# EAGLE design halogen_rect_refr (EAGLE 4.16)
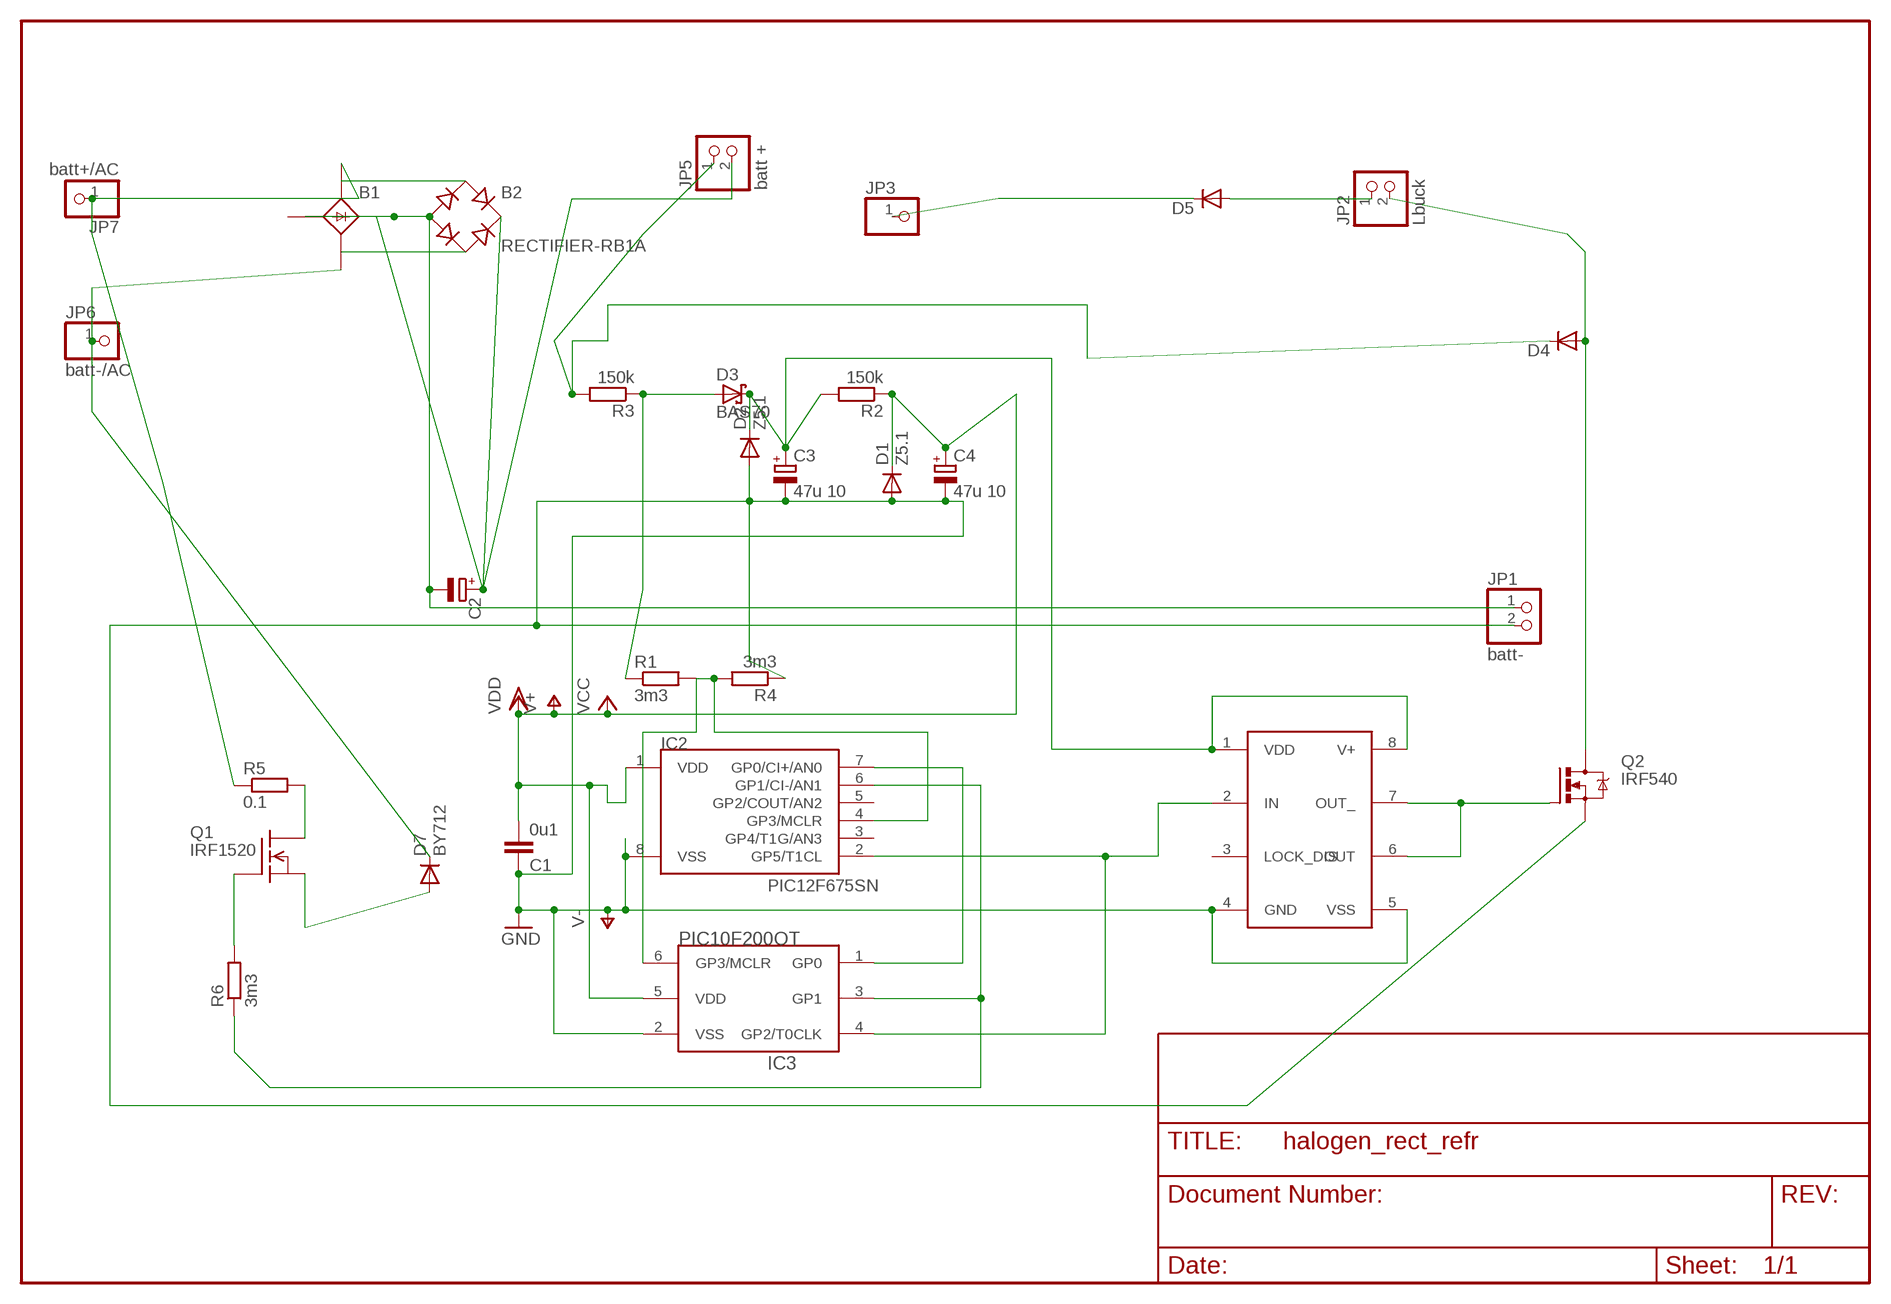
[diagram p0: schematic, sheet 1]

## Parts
B1  B25A-  [B25A-]
B2  RECTIFIER-RB1A  [RB1A]
C1  0u1  C-EUC1206  [C1206]
C2  CPOL-EUE7.5-18  [E7,5-18]
C3  47u 10  CPOL-EUE2,5-6E  [E2,5-6E]
C4  47u 10  CPOL-EUSMCD  [SMC_D]
D1  Z5.1  DIODE-MINIMELF  [MINIMELF]
D2  Z5.1  DIODE-MINIMELF  [MINIMELF]
D3  BAS70  [SOT23]
D4  DIODE-MELF-MLL41  [MELF-MLL41]
D5  DIODE-MELF-MLL41  [MELF-MLL41]
D7  BY712  [SOD61E]
IC1  TC4432X  [SO-08]
IC2  PIC12F675SN  [SO-08]
IC3  PIC10F200OT  [SOT23-6]
JP1  batt-  PINHD-1X2  [1X02]
JP2  Lbuck  PINHD-1X2  [1X02]
JP3  PINHD-1X1  [1X01]
JP5  batt +  PINHD-1X2  [1X02]
JP6  batt-/AC  PINHD-1X1  [1X01]
JP7  batt+/AC  PINHD-1X1  [1X01]
Q1  IRF1520  IRF540  [TO220]
Q2  IRF540  [TO220BV]
R1  3m3  R-EU_R1206  [R1206]
R2  150k  R-EU_R1206  [R1206]
R3  150k  R-EU_R1206  [R1206]
R4  3m3  R-EU_R1206  [R1206]
R5  0.1  R-EU_0613/5V  [P0613V]
R6  3m3  R-EU_R1206  [R1206]

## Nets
N$1: D4.C JP5.1 R3.2
N$2: B1.AC1-(AC1) JP7.1 R5.1
N$3: B1.AC2-(AC2) D7.C JP6.1
N$4: C3.+ D2.C D3.3(C) IC1.1(VDD) IC1.8(V+) R2.2
N$5: D5.A JP2.1
N$6: D3.1(A) R1.1 R3.1
N$7: IC1.6(OUT) IC1.7(OUT_) Q2.G
N$8: B1.AC1 B2.AC1
N$9: D4.A JP2.2 Q2.D
N$10: B1.+ B2.+ C2.+ JP5.2
N$11: B1.AC2 B2.AC2
N$12: IC2.4(GP3/MCLR) IC3.6(GP3/MCLR) R1.2 R4.2
N$13: B1.+1(+) B1.- B2.- C2.- JP1.1
N$14: IC1.2(IN) IC2.2(GP5/T1CL) IC3.4(GP2/T0CLK)
N$15: IC2.7(GP0/CI+/AN0) IC3.1(GP0)
N$16: IC2.6(GP1/CI-/AN1) IC3.3(GP1) R6.1
N$20: D7.A Q1.3(S)
N$21: Q1.2(D) R5.2
N$24: D5.C JP3.1
N$25: Q1.1(G) R6.2
V+: C1.2 C4.+ D1.C IC2.1(VDD) IC3.5(VDD) R2.1 ; supply symbol labelled VCC, VDD
V-: C1.1 C3.- C4.- D1.A D2.A IC1.4(GND) IC1.5(VSS) IC2.8(VSS) IC3.2(VSS) JP1.2 Q2.S R4.1 ; supply symbol labelled GND
Unconnected: B1.-1(-) IC1.3(LOCK_DIS) IC2.3(GP4/T1G/AN3) IC2.5(GP2/COUT/AN2)

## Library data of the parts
B1 = rectifier:B25A-: RECTIFIER 25-A bridge
B2 = rectifier:RECTIFIER-: Rectifier
C1 = rcl:C-EU: CAPACITOR, European symbol
C2-C4 = rcl:CPOL-EU: POLARIZED CAPACITOR, European symbol
D1 D2 D4 D5 = diode:DIODE-: DIODE
D3 = diode:BAS70: Silicon Schottky Diodes
D7 = diode:BY712: DIODE
IC1 = microchip:TC4432
IC2 = microchip-3:PIC12F6*: uPC nW 1k Program Flash memory 2x Timer Comparator 10b A/D converter/ 4xIN
IC3 = microchip-3:PIC10F20*: uPC nW 0,25/0,5k Program Flash memory
JP1 JP2 JP5 = pinhead:PINHD-1X2: PIN HEADER
JP3 JP6 JP7 = pinhead:PINHD-1X1: PIN HEADER
Q1 = transistor-fet:IRF540: N-Channel Enhancement MOSFET (HEXFET); 100V; 28A; 0,077Ohm
Q2 = transistor-power:IRF540: HEXFET Power MOSFET
R1-R6 = rcl:R-EU_: RESISTOR, European symbol

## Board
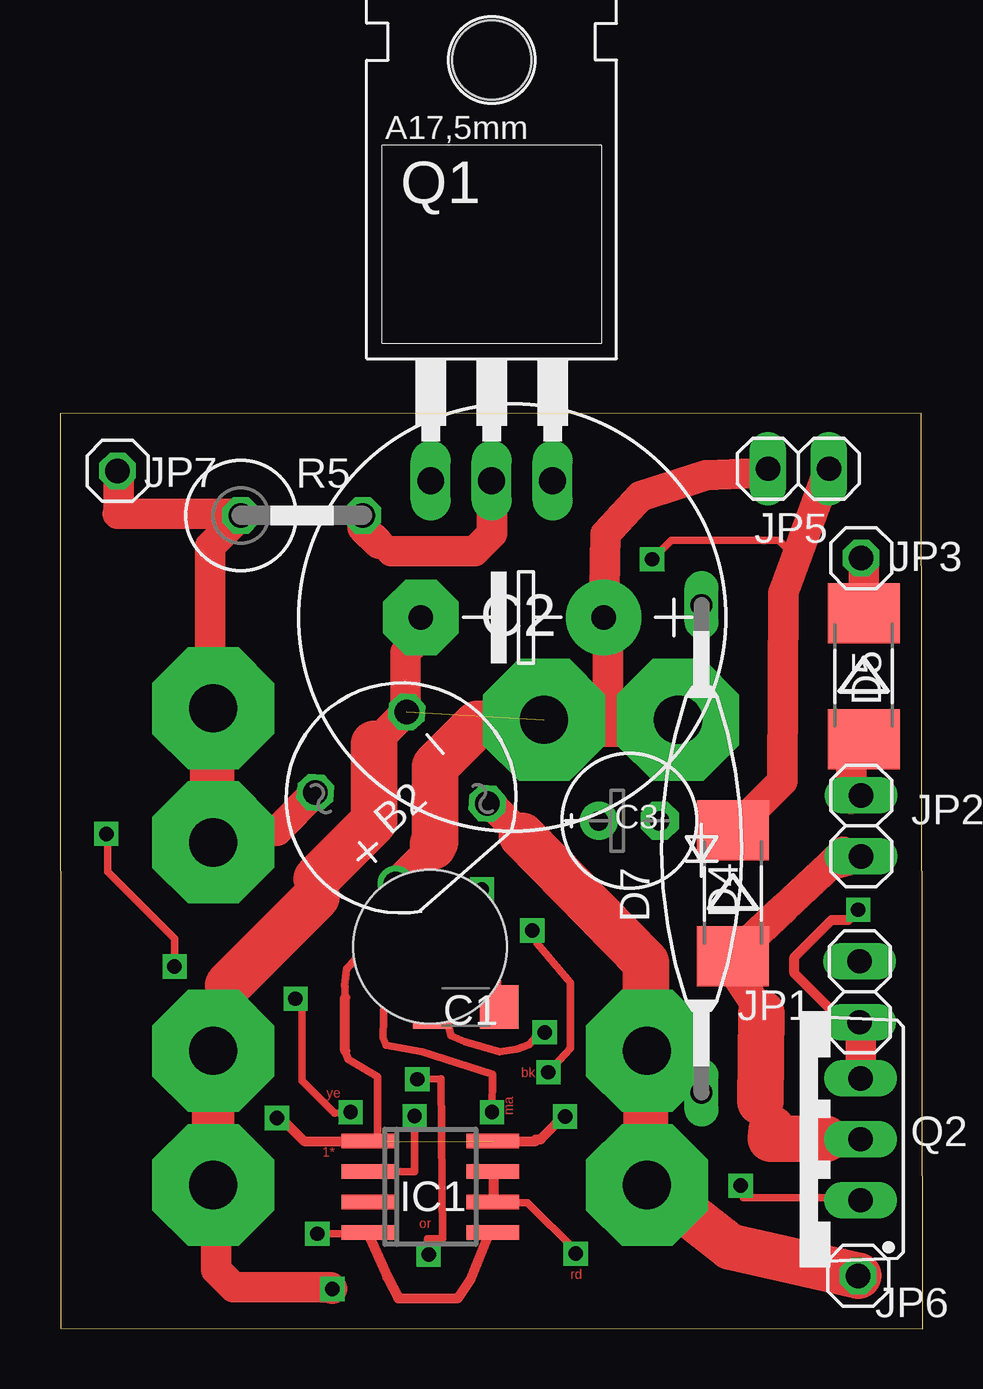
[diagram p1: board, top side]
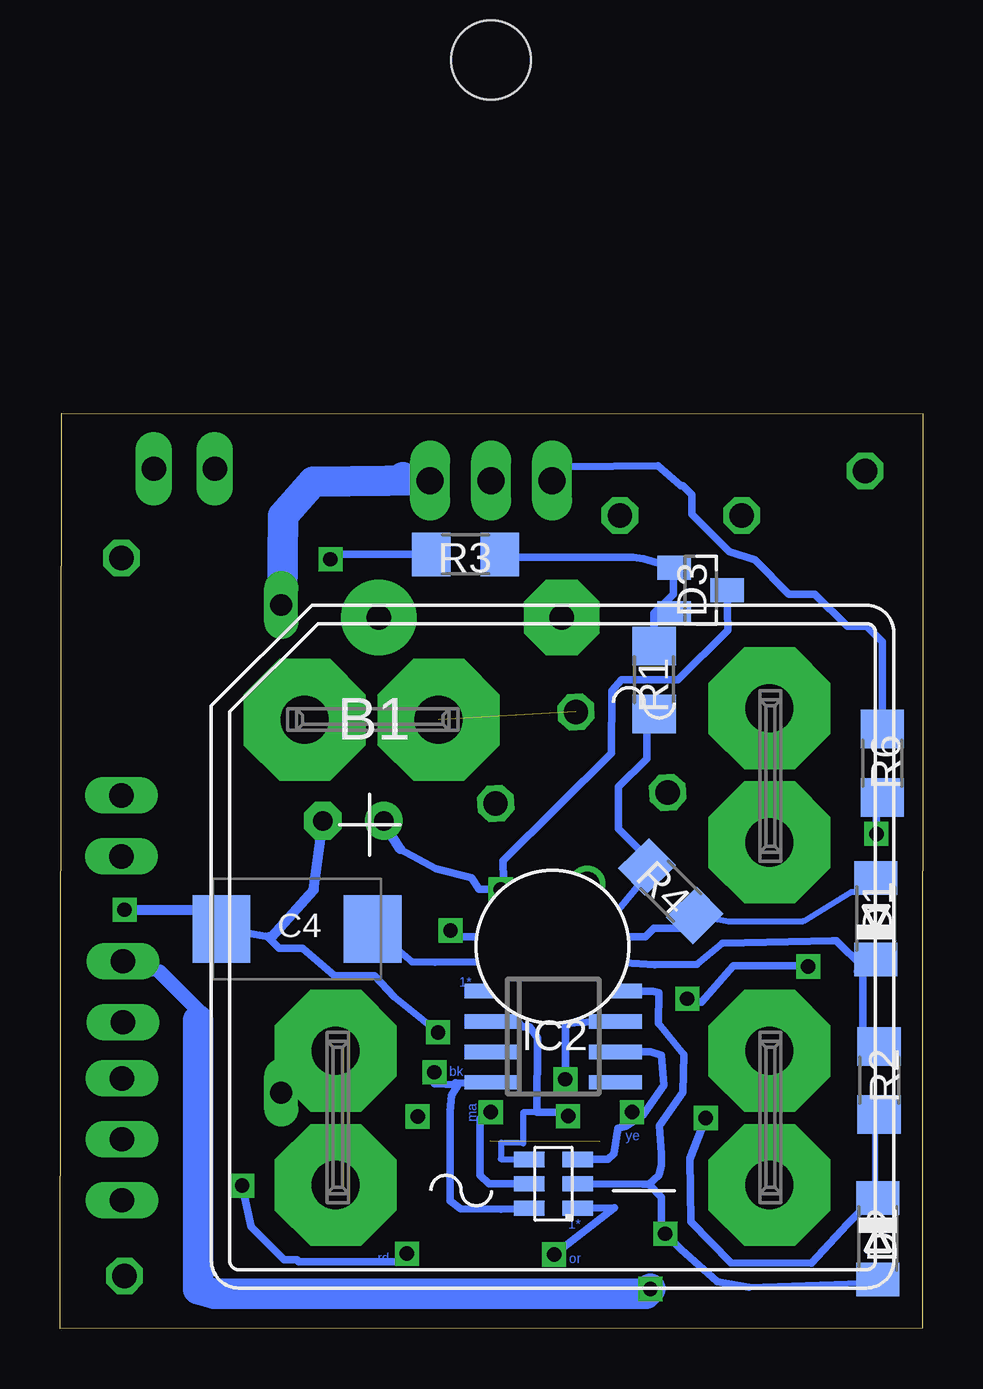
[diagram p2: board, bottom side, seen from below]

Size 35.97 x 38.15 mm. Coordinates in mm from the lower left corner, seen from the top.
Outline: 0.03,0.01 35.97,0 35.9,38.15 0,38.13 0.03,0.01
Copper layers (1*16): Top 0.035mm / dielectric 1.5mm / Bottom 0.035mm
Design rules "default": minimum track width 10mil, minimum drill 24mil, track to track 8mil, track to pad 8mil, pad to pad 8mil, via to via 8mil, smd to smd 8mil, copper to edge 40mil, drill to drill 8mil, minimum pad ring 10mil, minimum via ring 8mil, stop-mask expansion 4mil, vias tented up to drill 0mil, thermal gap 10mil

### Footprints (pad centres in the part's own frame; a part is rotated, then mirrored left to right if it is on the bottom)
B25A- = drill 2.007 pad 5.08 octagon: + -10.338,9.449; +1 -4.75,9.449; - 9.042,-4.343; -1 9.042,-9.931; AC1 9.042,4.343; AC1- 9.042,9.931; AC2 -9.042,-4.343; AC2- -9.042,-9.931 | hole 6.401: 0,0
RB1A = drill 1.016 round: + -2.54,2.54 | drill 1.016 octagon: - 2.54,-2.54; AC1 2.54,2.54; AC2 -2.54,-2.54
C1206 = smd 1.6 x 1.8: 1 -1.4,0; 2 1.4,0
E7,5-18 = drill 1.016 pad 3.15 round: + -3.81,0 | drill 1.016 pad 3.15 octagon: - 3.81,0
E2,5-6E = drill 0.813 pad 1.575 round: + -1.27,0 | drill 0.813 pad 1.575 octagon: - 1.27,0
SMC_D = smd 2.4 x 2.8: + -3.15,0; - 3.15,0
MINIMELF = smd 1.4 x 1.8: A 1.7,0; C -1.7,0
SOT23 = smd 1 x 1.4: 1 -0.95,-1.1; 2 0.95,-1.1; 3 0,1.1
MELF-MLL41 = smd 2.5 x 3: A 2.625,0; C -2.625,0
SOD61E = drill 0.914 long: A 10.16,0; C -10.16,0
SO-08 = smd 0.6 x 2.2: 1 -1.905,-2.6; 2 -0.635,-2.6; 3 0.635,-2.6; 4 1.905,-2.6; 5 1.905,2.6; 6 0.635,2.6; 7 -0.635,2.6; 8 -1.905,2.6
SOT23-6 = smd 0.635 x 1.27: 1 -1.016,-1.016; 2 0,-1.016; 3 1.016,-1.016; 4 1.016,1.016; 5 0,1.016; 6 -1.016,1.016
1X02 = drill 1.016 long: 1 -1.27,0; 2 1.27,0
1X01 = drill 1.016 octagon: 1 0,0
TO220 = drill 1.118 long: 1 -2.54,-6.35; 2 0,-6.35; 3 2.54,-6.35 | hole 3.302: 0,11.176
TO220BV = drill 1.016 long: D 0,-2.54; G -2.54,-2.54; S 2.54,-2.54
R1206 = smd 1.6 x 1.803: 1 -1.422,0; 2 1.422,0
P0613V = drill 1.016 octagon: 1 -2.54,0; 2 2.54,0

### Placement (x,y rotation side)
B1  15.43,15.92 0 bottom
B2  14.22,22.12 131.3 top
C1  16.92,13.41 0 top
C2  18.86,29.64 180 top
C3  23.74,21.17 0 top
C4  26.09,16.66 180 bottom
D1  1.96,17.09 90 bottom
D2  1.87,3.75 270 bottom
D3  9.26,30.77 270 bottom
D4  28.05,18.14 270 top
D5  33.5,27.2 270 top
D7  26.75,20 90 top
IC1  15.44,5.91 270 top
IC2  15.41,12.17 270 bottom
IC3  15.39,6.04 90 bottom
JP1  33.34,14.04 270 top
JP2  33.4,20.95 270 top
JP3  33.4,32.11 0 top
JP5  30.78,35.83 180 top
JP6  33.27,2.2 0 top
JP7  2.4,35.75 0 top
Q1  18,41.69 0 top
Q2  30.84,7.89 90 top
R1  11.2,27.03 270 bottom
R2  1.82,10.35 270 bottom
R3  19.06,32.27 180 bottom
R4  10.5,18.23 134.6 bottom
R5  10.08,33.89 0 top
R6  1.69,23.57 90 bottom

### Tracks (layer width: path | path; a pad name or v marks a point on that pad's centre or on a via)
N$1  (via drill 0.6)
  Top 0.305: v24.69,32.06 25.49,32.86 29.96,32.86 30.57,32.25 30.74,32.25
  Top 1.27: JP5.1 30.74,32.25 30.16,30.67 30.11,22.82 D4.C | D4.C | D4.C 28.05,20.66
  Bottom 0.305: R3.2 24.49,32.27 v24.69,32.06
N$2
  Top 1.27: B1.AC1- 6.26,25.98 6.26,32.61 7.26,33.61 7.26,33.82 7.47,33.82 R5.1 7.47,33.97 2.4,33.97 2.45,34.02 2.45,35.72 2.43,35.72 JP7.1
N$3
  Top 1.27: 24.47,11.07 24.54,11.13 24.54,11.17 25.41,11.17 D7.C
  Top 1.778: B1.AC2- 24.47,6.23 | 24.47,6.23 24.47,11.07 24.37,11.17 24.37,6.33 24.47,6.23 | 24.47,6.23 24.7,6 24.7,5.95
  Top 1.93: JP6.1 27.94,3.41 24.7,5.95
N$4  (via drill 0.6)  (1 unrouted)
  Top 0.305: v17.59,18.31 17.4,18.36 13.77,16.91 11.95,14.99 11.86,14.3 11.86,14.27 11.89,14.24 11.89,13.81 | 11.89,11.58 12,11.22 13.25,10.51 13.25,7.83 13.45,7.79 13.45,7.72 12.84,7.72 | 12.84,7.72 12.83,7.72 | IC1.1 12.84,7.72
  Top 0.406: v9.04,8.78 9.31,8.69 10.19,7.82 IC1.1 | 11.89,11.58 11.89,13.81 | IC1.8 19.84,7.82 19.84,7.89 20.04,7.89 20.99,8.85
  Bottom 0.254: D2.C 1.97,6.01 1.97,8.3 R2.2
  Bottom 0.305: v9.04,8.78 9.7,7.08 9.66,4.45 8,2.75 4.64,2.74 3.14,4.35 1.97,5.49 1.91,5.49 D2.C | 17.5,17.86 17.53,17.84 | 17.5,17.86 v17.59,18.31 18.5,18.32 18.81,18.79 20.29,19.16 21.78,19.98 | 17.5,17.86 17.46,17.9 17.5,19.5 12.97,23.99 12.95,26.59 12.56,27.03 10.2,27.03 8.12,29.11 D3.3
  Bottom 0.406: C3.+ 22.43,21 21.78,19.98
N$5
  Top 1.27: D5.A 32.97,24.01 32.98,24.01 32.98,22.08 JP2.1
N$6
  Bottom 0.305: R1.1 11.2,29.8 10.39,30.61 10.39,31.59 10.32,31.53 | 10.32,31.53 10.32,31.77 | 10.32,31.53 D3.1 11.65,32.09 12.08,32.14 17.75,32.14 17.81,32.19 17.73,32.27 R3.1
N$7  (via drill 0.6)
  Top 0.305: 18.1,5.28 18.12,5.25 19.49,5.25 21.5,3.25 v21.5,3.13 | 33.48,5.46 33.52,5.46 | 33.48,5.46 Q2.G | v28.37,5.96 28.49,5.46 33.48,5.46
  Top 0.406: IC1.7 18.1,6.55 18.1,5.28 IC1.6
  Bottom 0.305: v21.5,3.13 21.84,2.79 26.01,2.79 26.09,2.87 26.62,2.87 28,4.25 v28.37,5.96
N$8
  Top 1.27: B2.AC1 9.05,20.76 6.18,20.76
  Top 1.778: 6.3,20.18 6.3,20.65 | 6.3,20.65 6.3,25.76 6.39,25.85 6.39,20.45 6.3,20.37 | 6.3,20.37 6.12,20.19 | 6.3,20.65 6.3,20.37
  Top 1.93: 6.3,19.95 6.3,20.18 B1.AC1 | 6.3,20.65 6.18,20.76
N$9
  Top 1.27: 31.93,7.92 Q2.D | 29.2,9.47 29.67,8.34 | 29.25,13.18 28.33,14.51 28.33,15.6 28.14,15.6 D4.A 30.22,17.57 32.07,19.3 | 32.07,19.3 32.66,19.87 | 32.07,19.3 JP2.2
  Top 1.93: 31.93,7.92 29.63,7.92 29.67,8.34 | 29.2,9.47 29.25,13.18
N$10
  Top 1.27: B2.+ 15.56,20.1 | 23.14,25.2 22.83,25.51 22.83,30.5 22.68,30.5 C2.+ 22.73,33.1 24.19,34.68 26.94,35.57 29.41,35.67 29.41,35.73 JP5.2
  Top 1.93: 15.56,20.1 15.56,20.2 15.63,20.28 15.63,23.44 17.4,25.2 23.14,25.2 25.72,25.2 25.72,25.32 B1.+
N$11
  Top 1.27: 19.27,20.54 17.92,21.89 B2.AC2
  Top 1.93: 24.42,11.53 24.42,11.08 | B1.AC2 24.42,11.53 | 19.27,20.54 24.42,15.27 24.42,11.53
N$12  (via drill 0.6)
  Top 0.305: v19.68,16.59 19.89,16.07 21.27,14.42 21.27,11.68 v20.36,10.69
  Bottom 0.305: IC3.6 17.59,4.99 19.27,5 19.7,5.33 19.71,9.05 19.65,9.74 19.35,10.18 19.48,10.24 | IC2.4 17.94,10.32 18.15,10.23 18.99,10.23 19.48,10.24 | v19.68,16.59 19.28,16.33 16.88,16.33 16.15,17.08 15.86,17.28 15.63,17.22 12.89,17.22 11.5,18.9 R4.2 11.5,19.65 12.69,20.84 12.69,22.58 11.51,23.76 11.51,25.41 11.26,25.65 11.23,25.61 R1.2 | 19.48,10.24 19.48,10.17 20.36,10.21 v20.36,10.69
N$13  (via drill 0.6)  (1 unrouted)
  Top 0.406: 6.39,5.81 6.54,5.66 6.54,5.74 6.54,11.93 7,12.39 7.01,12.39
  Top 1.27: 13.09,24.38 14.42,25.7 B2.- 14.4,25.76 14.4,28.19 15.15,28.94 15.15,29.6 15.09,29.6 C2.- | 10.69,17.99 10.69,18.75 | 6.39,11.77 B1.- | 7.01,12.39 7.01,14.31 | v11.35,1.66 11.29,1.72 7.24,1.72 6.5,2.46 6.5,5.74 6.54,5.74
  Top 1.778: 6.39,5.81 6.39,11.77
  Top 1.93: 13.09,24.38 13.09,21.15 10.69,18.75 | 7.01,14.31 10.69,17.99
  Bottom 0.406: 30.21,12.86 30.21,13.28 | JP1.1 33.34,15.26 32.94,14.87 31.8,14.87
  Bottom 0.61: 30.21,13.28 31.8,14.87
  Bottom 1.27: 30.21,12.86 30.21,1.65 29.54,1.47 11.54,1.47 v11.35,1.66
N$14  (via drill 0.6)
  Top 0.305: IC1.2 12.84,6.54 14.78,6.54 v14.78,8.86
  Bottom 0.254: IC3.4 17.59,7.07 17.58,7.75 16.66,7.73 16.66,9.01 14.96,9.01
  Bottom 0.305: v14.78,8.86 14.96,9.01 16.08,9.02 16.07,12.12 16.4,12.59 16.67,12.59 16.93,12.85 18.03,12.85 IC2.2
N$15  (via drill 0.6)
  Top 0.305: v15.37,3.09 15.33,3.75 15.94,3.75 15.87,10.41 v14.9,10.4
  Bottom 0.305: IC3.1 12.85,5.05 v15.37,3.09 | IC2.7 13.2,12.81 14.9,12.73 v14.9,10.4
N$16  (via drill 0.6)
  Top 0.305: v12.12,9.02 11.46,8.97 10.1,10.33 10.1,13.27 v9.82,13.75 | v4.78,15.1 4.78,16.25 1.98,19.05 1.98,20.57 v1.93,20.62
  Bottom 0.305: IC2.6 11.35,11.54 10.9,11.39 10.79,10.16 11.62,8.95 v12.12,9.02 11.65,8.92 12.37,8.44 12.7,8.35 12.88,7.3 13.12,7.06 14.16,7.06 14.17,7.04 14.19,7.06 IC3.3 | v9.82,13.75 9.23,13.61 7.89,15.13 5.31,15.13 v4.78,15.1 | R6.1 1.8,22.14 1.93,22.02 v1.93,20.62
N$19  (via drill 0.6)
  other vias: 21.06,8.85
N$20
  Bottom 1.27: D7.A 26.71,30.2 26.71,30.35 26.67,33.88 25.41,35.3 22.31,35.34 21.67,35.35 | 21.67,35.35 21.67,35.48 | 21.67,35.35 Q1.3
N$21
  Top 0.406: 13.3,32.71 13.5,32.71 13.82,32.39
  Top 1.27: R5.2 12.62,33.38 13.3,32.71 | Q1.2 18,35.29 18.08,35.2 18.01,35.12 18.01,33.12 17.28,32.39 13.82,32.39
N$24
  Top 1.27: JP3.1 33.4,32.21 33.5,32.11 D5.C
N$25
  Bottom 0.305: R6.2 1.69,28.63 2.32,29.27 3.15,29.27 4.5,30.61 5.58,30.61 7,32.04 8.05,32.37 9.61,33.93 9.61,34.74 10.01,35.14 10.07,35.14 11.04,35.95 14.76,35.92 15.56,35.49 Q1.1
V+  (via drill 0.6)
  Top 0.305: v14.48,15.43 14.83,16.29 16.75,16.94 17.89,15.98 v17.96,15.3 18,15.3 18.01,15.31 18.18,15.14 C1.2 | v18.01,9.02 18.02,10.61 15.1,11.55 13.59,11.81 13.47,12.12 13.53,14.52 14.47,15.55 | 14.47,15.55 14.52,15.55 | v14.48,15.43 14.47,15.55 | v14.49,15.43 14.5,15.44 | v14.48,15.43 v14.49,15.43 | v14.49,15.43 14.43,15.36
  Bottom 0.254: D1.C 2.48,15.06 2.73,14.9 | R2.1 2.44,12.33 2.48,12.36
  Bottom 0.305: v14.48,15.43 13.13,15.3 11.16,15.17 9.42,15.18 8.36,16.06 3.76,16.17 3.59,16.17 2.48,15.06 | 17.91,14.08 17.88,14.05 | 17.91,14.08 IC2.1 18,14.45 17.94,14.51 17.94,15.18 18,15.24 | 17.91,14.08 17.93,14.1 v17.96,15.3 20.33,15.27 21.28,15.29 C4.+ | IC3.5 18.07,6.04 18.47,6.4 18.45,8.75 v18.01,9.02 | 2.73,14.9 2.63,14.9 2.49,14.77 2.49,12.28 2.44,12.33
V-  (via drill 0.6)
  Top 0.254: v20.21,12.35 19.82,12.21 19.85,12.16
  Top 0.305: IC1.4 12.79,3.96 v10.73,3.96 | 19.85,12.16 19.55,11.84 19.02,11.65 18.33,11.54 16.88,11.96 16.29,12.2 16.19,12.63 16.13,12.7 C1.1 15.38,14.15 16.22,14.99 v16.22,15.34
  Top 0.406: IC1.5 17.91,4.01 17.13,2.08 16.6,1.28 14.11,1.27 13.65,2.14 12.81,4.01 IC1.4 | 33.38,12.85 33.36,12.86 33.34,12.83 JP1.2 32.65,12.77 30.62,14.8 30.62,15.49 32.17,17.04 32.85,17.04 v33.27,17.46
  Top 1.27: Q2.S 33.38,12.85
  Bottom 0.254: 7.24,1.72 1.93,1.91 D2.A | D1.A 2.73,18.21 2.98,18.21 4.98,16.99 8.09,16.97 R4.1
  Bottom 0.305: D2.A | 7.24,1.72 8.56,1.95 10.08,3.31 v10.73,3.96 | IC3.2 11.66,6.01 11.42,6.01 | v10.73,3.96 10.69,3.92 10.69,3.88 10.73,3.88 | 10.73,3.88 10.91,3.88 | IC2.8 12.85,14.03 | IC2.8 | IC2.8 12.78,14.1 | 9.1,17.22 R4.1 10,16.69 11.2,16.69 11.56,16.33 13.12,16.33 13.32,16.53 15.37,16.53 15.79,16.11 15.85,16.11 16.28,15.68 16.22,15.62 v16.22,15.34 16.22,14.94 15.34,14.07 13.25,14.07 13.22,14.04 13.18,14.08 IC2.8 | 27.28,16.34 27.23,16.33 | 27.28,16.34 C4.- | v20.21,12.35 22.03,13.83 22.85,14.71 24.52,14.71 25.84,15.86 26.82,15.86 27.28,16.31 27.28,16.32 27.28,16.34 | 11.42,6.01 10.88,5.48 10.88,4.03 10.73,3.88 | v10.73,3.96 10.73,3.88 | 11.42,6.01 11,6.4 10.88,6.82 10.9,7.28 10.98,8.46 9.99,9.85 9.96,11.41 11.01,12.72 11,13.99 11.25,14.05 12.24,14.05 12.28,14.19 12.86,14.19 12.86,14.14 IC2.8
  Bottom 0.406: C3.- 25.39,18.28 27.15,16.34 27.23,16.33 | 29.16,16.38 29.24,16.45 | 29.24,16.45 C4.- | v33.27,17.46 30.24,17.46 29.24,16.45

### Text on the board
Top: ye | ma | bk | 1* | or | rd
Bottom: 1* | bk | ma | ye | 1* | or | rd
